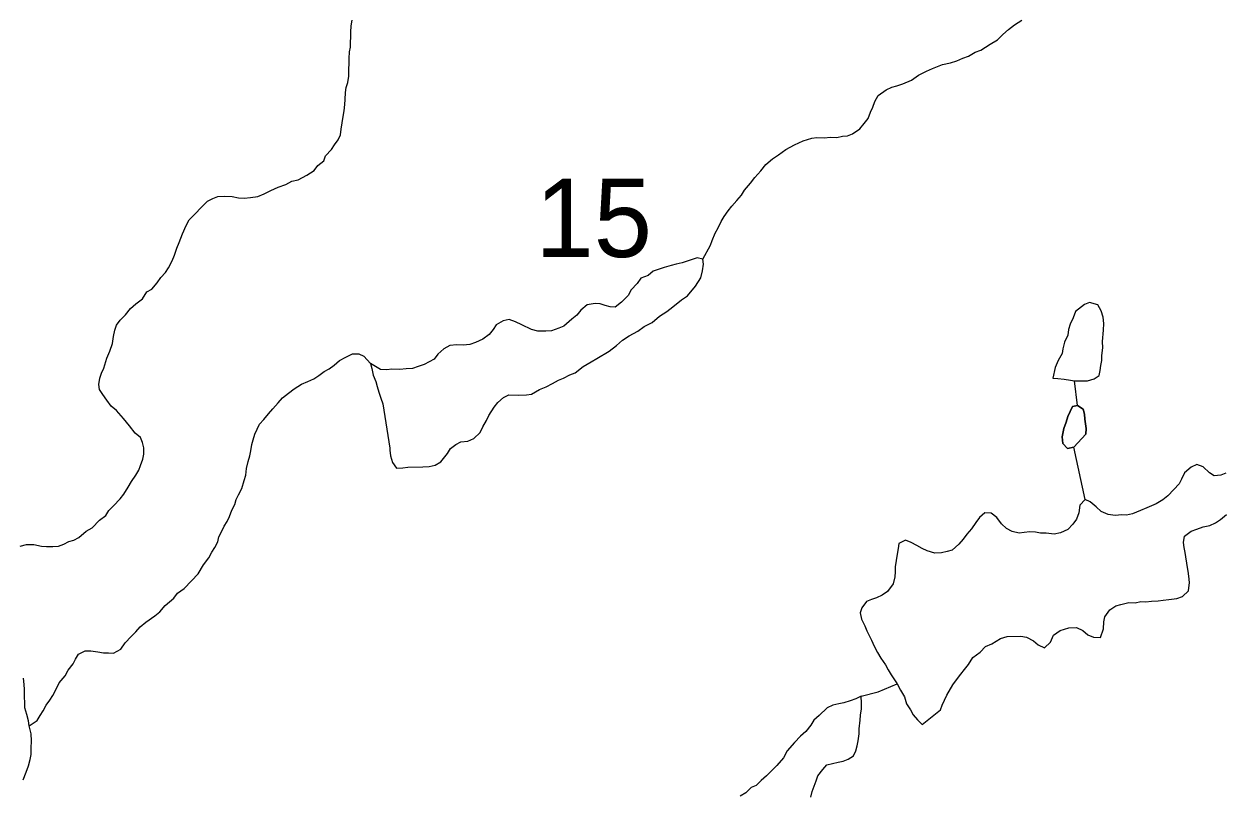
# Model space of a CAD drawing. Extents: x 0 to 34, y -4 to 22.
# Drawn here: x 7.9963 to 8.4463, y 18.567 to 18.8564 of the extents above; entities that cross this region are included whole.
import ezdxf

# ---------------------------------------------------------------- set-up
doc = ezdxf.new("R2010")
doc.units = 0
for name, color, linetype in [('GM_X_Minor_Lake', 7, 'Continuous'), ('GM_X_Minor_River', 7, 'Continuous'), ('GM_X_Section_Text', 7, 'Continuous')]:
    doc.layers.add(name, color=color, linetype=linetype)

msp = doc.modelspace()

# ---------------------------------------------------------------- linework, layer by layer
at = {"layer": 'GM_X_Minor_Lake'}
for points in [[(8.14615, 18.69014), (8.14857, 18.69034), (8.15073, 18.6908), (8.15291, 18.69207), (8.15543, 18.6952), (8.15656, 18.69703), (8.15848, 18.69858), (8.16039, 18.69959), (8.16308, 18.69977), (8.16525, 18.70077), (8.16774, 18.7031), (8.16862, 18.70521), (8.17003, 18.70757), (8.1709, 18.70941), (8.17288, 18.71256), (8.17428, 18.71438), (8.17648, 18.71619), (8.17839, 18.7172), (8.18214, 18.71708), (8.18509, 18.71726), (8.18697, 18.71746), (8.18998, 18.71924), (8.19242, 18.72024), (8.19487, 18.7215), (8.19706, 18.72276), (8.19896, 18.72351), (8.20141, 18.72477), (8.20331, 18.72551), (8.20633, 18.72782), (8.20934, 18.7296), (8.21153, 18.73086), (8.21617, 18.73366), (8.21892, 18.73571), (8.22113, 18.73778), (8.22359, 18.73931), (8.22687, 18.74108), (8.22934, 18.74287), (8.23233, 18.74438), (8.23509, 18.7467), (8.23783, 18.74849), (8.24003, 18.75029), (8.24333, 18.75286), (8.24552, 18.75439), (8.24859, 18.75804), (8.25057, 18.76118), (8.25119, 18.76383), (8.25154, 18.76623), (8.25134, 18.7681), (8.24921, 18.7687), (8.2465, 18.76772), (8.24352, 18.76674), (8.24136, 18.76627), (8.23947, 18.7658), (8.23677, 18.76508), (8.2327, 18.7636), (8.23077, 18.76206), (8.22806, 18.76108), (8.22665, 18.75898), (8.22443, 18.75665), (8.22329, 18.75454), (8.2208, 18.75195), (8.21833, 18.75016), (8.21645, 18.75021), (8.2146, 18.75081), (8.21274, 18.7514), (8.21087, 18.75146), (8.20791, 18.75101), (8.20543, 18.74895), (8.20403, 18.74713), (8.2021, 18.74558), (8.19907, 18.743), (8.19717, 18.74226), (8.19446, 18.74128), (8.19231, 18.74108), (8.18936, 18.74117), (8.18697, 18.74178), (8.18328, 18.74349), (8.1809, 18.74463), (8.17852, 18.74551), (8.17636, 18.74504), (8.17363, 18.74352), (8.1725, 18.74169), (8.1711, 18.73986), (8.16863, 18.73807), (8.16591, 18.73682), (8.16374, 18.73608), (8.16133, 18.73589), (8.15892, 18.73596), (8.15623, 18.73578), (8.15405, 18.73451), (8.15183, 18.73244), (8.15043, 18.73062), (8.14662, 18.7286), (8.14445, 18.72786), (8.14228, 18.72713), (8.13986, 18.72693), (8.13745, 18.72674), (8.1345, 18.72683), (8.13262, 18.72662), (8.13021, 18.7267), (8.12654, 18.72895)], [(8.39096, 18.72248), (8.39584, 18.7225), (8.39827, 18.72323), (8.40019, 18.7245), (8.40052, 18.72636), (8.40085, 18.72822), (8.40118, 18.73008), (8.40124, 18.73195), (8.4016, 18.73488), (8.40142, 18.73729), (8.40183, 18.74155), (8.40191, 18.74395), (8.40172, 18.74636), (8.40099, 18.74879), (8.39973, 18.75097), (8.39654, 18.75187), (8.39464, 18.75112), (8.39134, 18.74855), (8.39046, 18.74618), (8.38931, 18.74381), (8.3887, 18.74169), (8.38836, 18.73956), (8.38721, 18.73693), (8.38659, 18.73454), (8.38626, 18.73268), (8.38484, 18.73005), (8.38368, 18.72742), (8.38275, 18.72344)], [(8.12654, 18.72895), (8.12701, 18.72706), (8.12746, 18.72465), (8.12846, 18.72221), (8.12893, 18.72033), (8.12966, 18.71817), (8.13039, 18.71601), (8.13113, 18.71385), (8.1337, 18.69724)], [(8.38275, 18.72344), (8.38461, 18.72338), (8.38701, 18.72304), (8.38941, 18.7227), (8.39096, 18.72248)], [(8.39073, 18.69755), (8.3883, 18.69709), (8.38649, 18.69901), (8.3863, 18.70142), (8.38694, 18.70461), (8.38782, 18.70699), (8.38843, 18.70911), (8.38929, 18.71095), (8.39016, 18.71279), (8.39205, 18.71327), (8.39415, 18.71187), (8.39462, 18.70998), (8.39483, 18.70811), (8.39525, 18.70462), (8.39518, 18.70249), (8.39073, 18.69755)], [(8.39073, 18.69755), (8.39518, 18.70249), (8.39525, 18.70462), (8.39483, 18.70811), (8.39462, 18.70998), (8.39415, 18.71187), (8.39205, 18.71327), (8.39016, 18.71279), (8.38929, 18.71095)], [(8.38929, 18.71095), (8.38843, 18.70911), (8.38782, 18.70699), (8.38694, 18.70461), (8.3863, 18.70142), (8.38649, 18.69901), (8.3883, 18.69709), (8.39073, 18.69755)], [(8.1337, 18.69724), (8.13377, 18.6964), (8.13396, 18.69426), (8.13469, 18.69183), (8.13622, 18.68965), (8.13864, 18.68984), (8.14052, 18.69005), (8.14615, 18.69014)], [(8.44774, 18.68777), (8.44584, 18.68703), (8.44342, 18.68684), (8.44158, 18.68796), (8.43924, 18.69017), (8.43686, 18.69105), (8.43468, 18.69005), (8.4322, 18.68799), (8.43105, 18.68562), (8.43019, 18.68377), (8.42825, 18.6817), (8.42603, 18.67936), (8.4241, 18.67782), (8.42164, 18.67629), (8.41811, 18.6748), (8.41566, 18.6738), (8.41267, 18.67256), (8.41051, 18.67209), (8.40864, 18.67215), (8.40622, 18.67196), (8.40356, 18.67231), (8.40091, 18.67346), (8.39909, 18.67512), (8.39675, 18.67706), (8.3949, 18.67792), (8.39296, 18.67584)], [(8.39296, 18.67584), (8.39259, 18.67291), (8.39171, 18.67054), (8.39031, 18.66871), (8.38837, 18.66663), (8.38565, 18.66538), (8.38322, 18.66492), (8.38028, 18.66528), (8.37814, 18.66535), (8.37628, 18.66567), (8.37414, 18.66574), (8.37199, 18.66554), (8.37011, 18.66533), (8.36745, 18.66594), (8.36534, 18.66708), (8.36352, 18.66874), (8.36173, 18.6712), (8.35964, 18.67286), (8.35723, 18.67294), (8.35529, 18.67113), (8.35389, 18.6693), (8.35221, 18.66695), (8.35053, 18.66486), (8.34913, 18.66304), (8.34747, 18.66122), (8.34498, 18.65889), (8.34309, 18.65842), (8.34093, 18.65795), (8.33851, 18.65776), (8.33559, 18.65865), (8.33374, 18.6595), (8.33164, 18.66064), (8.32953, 18.66177), (8.32742, 18.66264), (8.32497, 18.66138), (8.32464, 18.65952), (8.3243, 18.65739), (8.32395, 18.655), (8.3236, 18.6526), (8.32354, 18.65074), (8.32348, 18.64887), (8.32286, 18.64622), (8.32062, 18.64335), (8.3187, 18.64207), (8.31653, 18.64107), (8.31463, 18.64033), (8.31273, 18.63958), (8.31104, 18.63723), (8.31044, 18.63538), (8.3109, 18.63296), (8.31216, 18.63052), (8.3129, 18.62863), (8.31466, 18.6251), (8.31566, 18.62293), (8.31692, 18.62049), (8.31819, 18.61831), (8.31998, 18.61585), (8.32099, 18.61395), (8.322, 18.61205), (8.3243, 18.60877), (8.32556, 18.60633), (8.32709, 18.60388), (8.3278, 18.60118), (8.32933, 18.599), (8.33034, 18.5971), (8.33189, 18.59518), (8.33371, 18.59352)], [(8.43332, 18.65243), (8.43255, 18.65806), (8.43208, 18.65994), (8.43188, 18.66182), (8.43222, 18.66421), (8.43469, 18.666), (8.43686, 18.66674), (8.4393, 18.66773), (8.44173, 18.66819), (8.44391, 18.66919), (8.44582, 18.67047), (8.44803, 18.67227)], [(8.33371, 18.59352), (8.34058, 18.59892), (8.34118, 18.60077), (8.34205, 18.60261), (8.34291, 18.60446), (8.34518, 18.6084), (8.34658, 18.61022), (8.34826, 18.61231), (8.34966, 18.61413), (8.35106, 18.61596), (8.35275, 18.61858), (8.3555, 18.62063), (8.35745, 18.62271), (8.35989, 18.6237), (8.36317, 18.62574), (8.36561, 18.62646), (8.3707, 18.62657), (8.37283, 18.62624), (8.37547, 18.62482), (8.37729, 18.62343), (8.37967, 18.62229), (8.38188, 18.62436), (8.38304, 18.627), (8.38551, 18.62879), (8.38876, 18.62976), (8.39171, 18.62993), (8.39408, 18.62879), (8.3959, 18.62713), (8.39802, 18.62626), (8.40069, 18.62618), (8.40187, 18.62935), (8.40196, 18.63202), (8.40229, 18.63388), (8.40425, 18.63649), (8.40644, 18.63803), (8.40833, 18.6385), (8.4113, 18.63921), (8.41371, 18.63914), (8.41587, 18.6396), (8.41774, 18.63955), (8.41989, 18.63975), (8.42231, 18.63994), (8.42419, 18.64015), (8.42634, 18.64035), (8.42931, 18.64079), (8.43147, 18.64153), (8.43368, 18.6436), (8.43406, 18.64679), (8.43387, 18.6492), (8.43367, 18.65108), (8.43332, 18.65243)], [(8.29182, 18.56623), (8.29242, 18.56835), (8.29389, 18.57231), (8.29449, 18.57416), (8.29644, 18.57651), (8.29784, 18.57834), (8.3, 18.5788), (8.30216, 18.57927), (8.30405, 18.57975), (8.30595, 18.58049), (8.30787, 18.58176), (8.30873, 18.58361), (8.30933, 18.58546), (8.30966, 18.58732), (8.31001, 18.58998), (8.31008, 18.59185), (8.31045, 18.59504), (8.31051, 18.59691), (8.31086, 18.5993), (8.31093, 18.60144), (8.31075, 18.60412), (8.30884, 18.60311), (8.30667, 18.60237), (8.30424, 18.60165), (8.30235, 18.60117), (8.30019, 18.6007), (8.29801, 18.5997), (8.29497, 18.59686), (8.29304, 18.59505), (8.2919, 18.59321), (8.28995, 18.59087), (8.28802, 18.58906), (8.2858, 18.58672), (8.28301, 18.5836), (8.28159, 18.58097), (8.27908, 18.57811), (8.27714, 18.57604), (8.2752, 18.57422), (8.27327, 18.57241), (8.27133, 18.5706), (8.26943, 18.56986), (8.26749, 18.56779), (8.2653, 18.56652)]]:
    msp.add_lwpolyline(points, dxfattribs=at)
at = {"layer": 'GM_X_Minor_River'}
for points in [[(8.02953, 18.73648), (8.02989, 18.73915), (8.0305, 18.74153), (8.0311, 18.74338), (8.0325, 18.74521), (8.03445, 18.74729), (8.0364, 18.74963), (8.03833, 18.75144), (8.0408, 18.75324), (8.0425, 18.75585), (8.04441, 18.75686), (8.04636, 18.75921), (8.04777, 18.7613), (8.04943, 18.76312), (8.05057, 18.76495), (8.05199, 18.76758), (8.05287, 18.76969), (8.05376, 18.77234), (8.05463, 18.77444), (8.05581, 18.77762), (8.05725, 18.78078), (8.05839, 18.78288), (8.06061, 18.78521), (8.06283, 18.78755), (8.06532, 18.78988), (8.06723, 18.79089), (8.06913, 18.79163), (8.07182, 18.79181), (8.07449, 18.79173), (8.07688, 18.79112), (8.07903, 18.79106), (8.08144, 18.79125), (8.08414, 18.7917), (8.08658, 18.79269), (8.08903, 18.79395), (8.09175, 18.7952), (8.09473, 18.79618), (8.09692, 18.79745), (8.09935, 18.79791), (8.10262, 18.79968), (8.10536, 18.80146), (8.10676, 18.80329), (8.10896, 18.80509), (8.10956, 18.80694), (8.11178, 18.80928), (8.11291, 18.81111), (8.11431, 18.81294), (8.11517, 18.81478), (8.11551, 18.81691), (8.11586, 18.8193), (8.1162, 18.8217), (8.11654, 18.82382), (8.11689, 18.82622), (8.11695, 18.82809), (8.11704, 18.83075), (8.11737, 18.83261), (8.11797, 18.83447), (8.11831, 18.83686), (8.1184, 18.83953), (8.11847, 18.84166), (8.11853, 18.84353), (8.11861, 18.84593), (8.11894, 18.84779), (8.119, 18.84966), (8.11907, 18.85153), (8.11913, 18.8534), (8.11921, 18.8558), (8.11955, 18.85793)], [(8.25134, 18.7681), (8.25419, 18.77336), (8.25479, 18.77521), (8.25594, 18.77785), (8.25708, 18.77995), (8.25823, 18.78232), (8.25937, 18.78415), (8.26077, 18.78624), (8.26217, 18.78807), (8.26412, 18.79015), (8.26579, 18.79223), (8.26693, 18.79407), (8.26916, 18.79667), (8.27083, 18.79876), (8.27306, 18.80136), (8.27502, 18.8037), (8.27749, 18.80576), (8.27969, 18.8073), (8.28244, 18.80935), (8.28571, 18.81112), (8.28897, 18.81262), (8.29222, 18.81359), (8.2941, 18.8138), (8.29705, 18.81371), (8.2992, 18.81391), (8.30161, 18.81383), (8.30376, 18.8143), (8.30565, 18.81451), (8.30755, 18.81525), (8.31029, 18.81704), (8.31196, 18.81912), (8.31336, 18.82095), (8.31424, 18.82333), (8.31511, 18.82517), (8.31598, 18.82728), (8.31713, 18.82965), (8.32015, 18.83169), (8.32232, 18.8327), (8.32421, 18.83317), (8.32638, 18.83391), (8.32964, 18.83541), (8.33238, 18.83719), (8.33538, 18.8387), (8.33756, 18.83971), (8.33946, 18.84045), (8.34136, 18.84119), (8.34433, 18.8419), (8.34676, 18.84263), (8.34894, 18.84363), (8.35111, 18.84436), (8.35357, 18.84589), (8.35573, 18.84662), (8.35929, 18.84892), (8.36202, 18.85044), (8.36397, 18.85251), (8.36617, 18.85432), (8.36837, 18.85612), (8.37111, 18.8579)], [(7.99487, 18.66035), (7.9973, 18.66108), (7.99998, 18.661), (8.00291, 18.66037), (8.00478, 18.66031), (8.00719, 18.66024), (8.00934, 18.66044), (8.01124, 18.66118), (8.01315, 18.66219), (8.01504, 18.66267), (8.01695, 18.66368), (8.0197, 18.666), (8.02189, 18.66727), (8.02466, 18.67012), (8.02713, 18.67191), (8.02826, 18.67375), (8.02993, 18.67557), (8.03243, 18.67816), (8.03383, 18.67999), (8.03552, 18.68261), (8.03666, 18.68471), (8.03835, 18.68706), (8.03948, 18.68889), (8.04008, 18.69075), (8.04096, 18.69312), (8.04129, 18.69498), (8.04137, 18.69738), (8.0409, 18.69927), (8.04015, 18.70116), (8.03807, 18.70283), (8.03601, 18.70556), (8.03369, 18.70831), (8.03111, 18.71133), (8.02903, 18.71299), (8.02749, 18.71518), (8.02595, 18.71736), (8.02468, 18.71927), (8.02447, 18.72115), (8.02482, 18.72354), (8.02542, 18.72539), (8.02628, 18.72724), (8.02747, 18.73094), (8.02863, 18.73358), (8.02953, 18.73648)], [(7.99827, 18.59293), (8.00128, 18.59497), (8.00241, 18.59681), (8.00355, 18.59864), (8.00469, 18.60075), (8.00609, 18.60257), (8.00722, 18.60441), (8.00837, 18.60678), (8.00952, 18.60914), (8.01175, 18.61175), (8.01289, 18.61385), (8.01484, 18.61619), (8.01571, 18.61804), (8.01684, 18.61987), (8.01929, 18.62113), (8.02143, 18.62106), (8.0241, 18.62072), (8.02623, 18.62038), (8.02811, 18.62032), (8.02998, 18.62027), (8.03271, 18.62179), (8.03439, 18.62414), (8.03662, 18.62647), (8.03828, 18.62829), (8.03995, 18.63011), (8.04215, 18.63191), (8.04544, 18.63422), (8.04737, 18.63576), (8.04932, 18.6381), (8.05263, 18.64094), (8.05403, 18.64276), (8.0565, 18.64456), (8.05927, 18.64741), (8.06177, 18.65001), (8.06376, 18.65342), (8.06572, 18.65603), (8.06686, 18.65813), (8.068, 18.65996), (8.06914, 18.66207), (8.06947, 18.66393), (8.07061, 18.66603), (8.07147, 18.66787), (8.0726, 18.66971), (8.07347, 18.67155), (8.07435, 18.67393), (8.07549, 18.67603), (8.07609, 18.67788), (8.07695, 18.67972), (8.0781, 18.68209), (8.079, 18.685), (8.07961, 18.68712), (8.07996, 18.68952), (8.08058, 18.69217), (8.08119, 18.69429), (8.08151, 18.69615), (8.08186, 18.69854), (8.08246, 18.70039), (8.08306, 18.70251), (8.08393, 18.70435), (8.08479, 18.7062), (8.08646, 18.70801), (8.08814, 18.7101), (8.08981, 18.71192), (8.09176, 18.71426), (8.09343, 18.71608), (8.09563, 18.71788), (8.09782, 18.71942), (8.10056, 18.7212), (8.103, 18.7222), (8.10518, 18.7232), (8.1071, 18.72447), (8.10903, 18.72602), (8.11093, 18.72703), (8.11285, 18.7283), (8.11479, 18.73011), (8.11724, 18.73137), (8.11969, 18.73263), (8.1221, 18.73256), (8.12395, 18.7317), (8.12654, 18.72895)], [(8.39205, 18.71327), (8.39096, 18.72248)], [(8.3949, 18.67792), (8.39073, 18.69755)], [(7.99599, 18.5727), (7.99716, 18.5756), (7.99804, 18.57798), (7.99866, 18.58036), (7.99899, 18.58222), (7.99906, 18.58462), (7.99915, 18.58729), (7.99897, 18.58997), (7.99827, 18.59293), (7.99806, 18.59481), (7.99734, 18.59723), (7.99661, 18.59966), (7.99668, 18.60153), (7.99649, 18.60394), (7.99658, 18.60661), (7.99637, 18.60848), (7.99618, 18.61089)], [(8.31075, 18.60412), (8.31723, 18.60578), (8.3243, 18.60877)]]:
    msp.add_lwpolyline(points, dxfattribs=at)

# ---------------------------------------------------------------- texts
at = {"layer": 'GM_X_Section_Text'}
msp.add_text('15', height=0.029444, rotation=0, dxfattribs=at).set_placement((8.18843, 18.76896))

doc.saveas('drawing.dxf')
